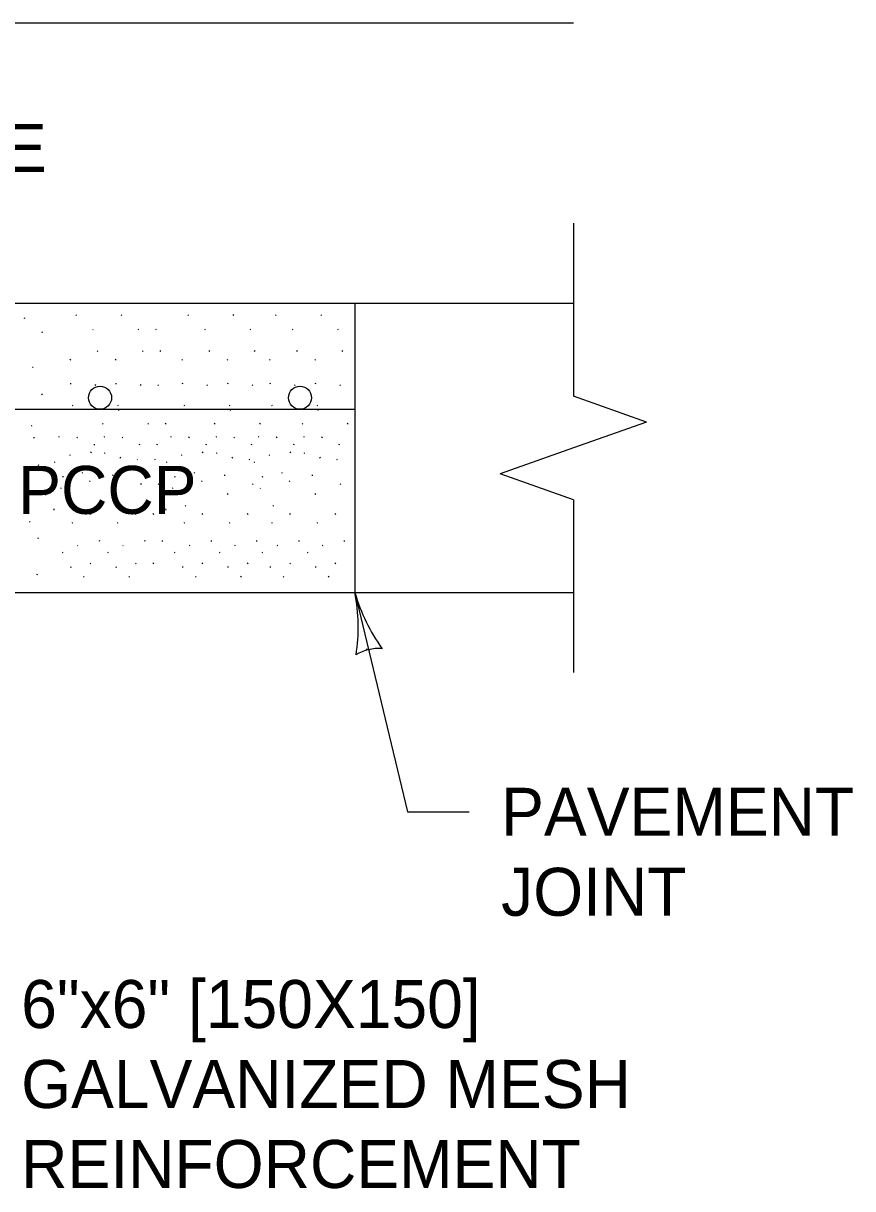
# Model space of a CAD drawing. Extents: x 49991.4 to 50029.7, y 49987.6 to 50011.4.
# Drawn here: x 50028.627 to 50029.664, y 49992.424 to 49993.881 of the extents above; entities that cross this region are included whole.
import ezdxf

# ---------------------------------------------------------------- set-up
doc = ezdxf.new("R2010")
doc.units = 0
for name, color, linetype in [('Level 1', 7, 'Continuous'), ('Level 2', 7, 'Continuous'), ('Level 3', 7, 'Continuous'), ('Level 4', 7, 'Continuous'), ('Level 5', 7, 'Continuous'), ('Level 6', 7, 'Continuous'), ('Level 9', 7, 'Continuous')]:
    doc.layers.add(name, color=color, linetype=linetype)

msp = doc.modelspace()

# ---------------------------------------------------------------- linework, layer by layer
at = {"layer": 'Level 1'}
for p, q in [((50028.0661, 49993.5314), (50029.3148, 49993.5314)), ((50029.0416, 49993.5313), (50029.0416, 49993.1697)), ((50028.0624, 49993.1696), (50029.3148, 49993.1696))]:
    msp.add_line(p, q, dxfattribs=at)
for centre in [(50028.723, 49993.4133), (50028.973, 49993.4133)]:
    msp.add_circle(centre, 0.0144, dxfattribs=at)
at = {"layer": 'Level 3'}
for p, q in [((50029.0416, 49993.1696), (50029.1073, 49992.8956)), ((50029.1073, 49992.8956), (50029.1845, 49992.8956))]:
    msp.add_line(p, q, dxfattribs=at)
for centre, radius, start, end in [((50028.8235, 49993.1267), 0.2223, 350.9492, 11.1327), ((50029.2652, 49993.2351), 0.233, 196.3205, 215.5704), ((50029.0715, 49993.045), 0.0548, 85.632, 121.3544)]:
    msp.add_arc(centre, radius, start, end, dxfattribs=at)
at = {"layer": 'Level 4'}
msp.add_line((50027.9165, 49993.3989), (50029.0416, 49993.3989), dxfattribs=at)
at = {"layer": 'Level 5'}
msp.add_line((50029.3148, 49993.8814), (50026.0794, 49993.8814), dxfattribs=at)
at = {"layer": 'Level 6'}
for p, q in [((50029.3148, 49993.6314), (50029.3148, 49993.4153)), ((50029.4062, 49993.3829), (50029.3148, 49993.4153)), ((50029.4062, 49993.3829), (50029.3148, 49993.3505)), ((50029.3148, 49993.3505), (50029.2234, 49993.3181)), ((50029.3148, 49993.2857), (50029.2234, 49993.3181)), ((50029.3148, 49993.2857), (50029.3148, 49993.0696))]:
    msp.add_line(p, q, dxfattribs=at)
at = {"layer": 'Level 9'}
for p, q in [((50028.6937, 49993.516), (50028.6927, 49993.5168)), ((50028.7504, 49993.516), (50028.7494, 49993.5168)), ((50028.8336, 49993.516), (50028.8326, 49993.5168)), ((50028.8902, 49993.516), (50028.8892, 49993.5168)), ((50028.9432, 49993.516), (50028.9422, 49993.5168)), ((50028.9999, 49993.516), (50028.9989, 49993.5168)), ((50028.6285, 49993.5134), (50028.6283, 49993.5121)), ((50028.6509, 49993.4951), (50028.65, 49993.4948)), ((50028.7146, 49993.4985), (50028.7138, 49993.4981)), ((50028.7712, 49993.4985), (50028.7704, 49993.4981)), ((50028.7932, 49993.4985), (50028.7924, 49993.4981)), ((50028.8545, 49993.4985), (50028.8537, 49993.4981)), ((50028.9111, 49993.4985), (50028.9103, 49993.4981)), ((50028.9641, 49993.4985), (50028.9633, 49993.4981)), ((50029.0207, 49993.4985), (50029.0199, 49993.4981)), ((50028.6864, 49993.4603), (50028.6853, 49993.4612)), ((50028.7203, 49993.4712), (50028.7193, 49993.4721)), ((50028.743, 49993.4603), (50028.742, 49993.4612)), ((50028.7769, 49993.4712), (50028.7759, 49993.4721)), ((50028.7989, 49993.4712), (50028.7979, 49993.4721)), ((50028.8262, 49993.4603), (50028.8252, 49993.4612)), ((50028.8602, 49993.4712), (50028.8592, 49993.4721)), ((50028.8828, 49993.4603), (50028.8818, 49993.4612)), ((50028.9168, 49993.4712), (50028.9158, 49993.4721)), ((50028.9359, 49993.4603), (50028.9348, 49993.4612)), ((50028.9698, 49993.4712), (50028.9688, 49993.4721)), ((50028.9925, 49993.4603), (50028.9915, 49993.4612)), ((50029.0264, 49993.4712), (50029.0254, 49993.4721)), ((50028.6394, 49993.4512), (50028.6386, 49993.4509)), ((50028.6861, 49993.4315), (50028.6859, 49993.4302)), ((50028.7176, 49993.4288), (50028.7166, 49993.4296)), ((50028.7428, 49993.4315), (50028.7426, 49993.4302)), ((50028.7743, 49993.4288), (50028.7733, 49993.4296)), ((50028.7962, 49993.4288), (50028.7952, 49993.4296)), ((50028.826, 49993.4315), (50028.8258, 49993.4302)), ((50028.8575, 49993.4288), (50028.8565, 49993.4296)), ((50028.8826, 49993.4315), (50028.8824, 49993.4302)), ((50028.9141, 49993.4288), (50028.9131, 49993.4296)), ((50028.9356, 49993.4315), (50028.9354, 49993.4302)), ((50028.9671, 49993.4288), (50028.9661, 49993.4296)), ((50028.9923, 49993.4315), (50028.9921, 49993.4302)), ((50029.0238, 49993.4288), (50029.0228, 49993.4296)), ((50028.6511, 49993.4171), (50028.6501, 49993.418)), ((50028.6889, 49993.4036), (50028.688, 49993.4033)), ((50028.7455, 49993.4036), (50028.7447, 49993.4033)), ((50028.8287, 49993.4036), (50028.8279, 49993.4033)), ((50028.8854, 49993.4036), (50028.8845, 49993.4033)), ((50028.9384, 49993.4036), (50028.9375, 49993.4033)), ((50028.995, 49993.4036), (50028.9942, 49993.4033)), ((50028.7464, 49993.3977), (50028.7456, 49993.3974)), ((50028.8863, 49993.3977), (50028.8855, 49993.3974)), ((50028.9959, 49993.3977), (50028.9951, 49993.3974)), ((50028.6377, 49993.378), (50028.6369, 49993.3776)), ((50028.727, 49993.3803), (50028.726, 49993.3811)), ((50028.7836, 49993.3803), (50028.7826, 49993.3811)), ((50028.8056, 49993.3803), (50028.8046, 49993.3811)), ((50028.8668, 49993.3803), (50028.8658, 49993.3811)), ((50028.9235, 49993.3803), (50028.9224, 49993.3811)), ((50028.9765, 49993.3803), (50028.9755, 49993.3811)), ((50029.0331, 49993.3803), (50029.0321, 49993.3811)), ((50028.6402, 49993.3641), (50028.6404, 49993.3627)), ((50028.672, 49993.3645), (50028.6712, 49993.3641)), ((50028.6948, 49993.363), (50028.6938, 49993.3638)), ((50028.7287, 49993.3645), (50028.7279, 49993.3641)), ((50028.7515, 49993.363), (50028.7505, 49993.3638)), ((50028.8119, 49993.3645), (50028.8111, 49993.3641)), ((50028.8347, 49993.363), (50028.8337, 49993.3638)), ((50028.8685, 49993.3645), (50028.8677, 49993.3641)), ((50028.8913, 49993.363), (50028.8903, 49993.3638)), ((50028.9215, 49993.3645), (50028.9207, 49993.3641)), ((50028.9443, 49993.363), (50028.9433, 49993.3638)), ((50028.9782, 49993.3645), (50028.9774, 49993.3641)), ((50029.001, 49993.363), (50029, 49993.3638)), ((50028.7122, 49993.3446), (50028.7112, 49993.3455)), ((50028.7157, 49993.3553), (50028.7155, 49993.354)), ((50028.7291, 49993.3438), (50028.7283, 49993.3435)), ((50028.7723, 49993.3553), (50028.7721, 49993.354)), ((50028.7943, 49993.3553), (50028.7941, 49993.354)), ((50028.852, 49993.3446), (50028.851, 49993.3455)), ((50028.8556, 49993.3553), (50028.8553, 49993.354)), ((50028.869, 49993.3438), (50028.8681, 49993.3435)), ((50028.9122, 49993.3553), (50028.912, 49993.354)), ((50028.9617, 49993.3446), (50028.9607, 49993.3455)), ((50028.9652, 49993.3553), (50028.965, 49993.354)), ((50028.9786, 49993.3438), (50028.9778, 49993.3435)), ((50029.0218, 49993.3553), (50029.0216, 49993.354)), ((50028.646, 49993.3294), (50028.6458, 49993.3281)), ((50028.6665, 49993.3328), (50028.6657, 49993.3324)), ((50028.6855, 49993.3414), (50028.6847, 49993.341)), ((50028.7491, 49993.3379), (50028.7481, 49993.3388)), ((50028.77, 49993.3361), (50028.7692, 49993.3358)), ((50028.792, 49993.3361), (50028.7912, 49993.3358)), ((50028.8064, 49993.3328), (50028.8056, 49993.3324)), ((50028.8254, 49993.3414), (50028.8246, 49993.341)), ((50028.8889, 49993.3379), (50028.8879, 49993.3388)), ((50028.9099, 49993.3361), (50028.9091, 49993.3358)), ((50028.916, 49993.3328), (50028.9152, 49993.3324)), ((50028.935, 49993.3414), (50028.9342, 49993.341)), ((50028.9986, 49993.3379), (50028.9976, 49993.3388)), ((50029.0195, 49993.3361), (50029.0187, 49993.3358)), ((50028.6763, 49993.3153), (50028.6765, 49993.3139)), ((50028.7016, 49993.3188), (50028.7006, 49993.3196)), ((50028.7388, 49993.317), (50028.7386, 49993.3156)), ((50028.8162, 49993.3153), (50028.8163, 49993.3139)), ((50028.8415, 49993.3188), (50028.8405, 49993.3196)), ((50028.8787, 49993.317), (50028.8785, 49993.3156)), ((50028.9258, 49993.3153), (50028.926, 49993.3139)), ((50028.9511, 49993.3188), (50028.9501, 49993.3196)), ((50028.9883, 49993.317), (50028.9881, 49993.3156)), ((50028.6743, 49993.3004), (50028.6735, 49993.3)), ((50028.7108, 49993.3086), (50028.7098, 49993.3095)), ((50028.7747, 49993.3048), (50028.7737, 49993.3057)), ((50028.7967, 49993.3048), (50028.7957, 49993.3057)), ((50028.8142, 49993.3004), (50028.8133, 49993.3)), ((50028.8507, 49993.3086), (50028.8497, 49993.3095)), ((50028.9146, 49993.3048), (50028.9136, 49993.3057)), ((50028.9238, 49993.3004), (50028.923, 49993.3)), ((50028.9603, 49993.3086), (50028.9593, 49993.3095)), ((50029.0242, 49993.3048), (50029.0232, 49993.3057)), ((50028.6553, 49993.2918), (50028.6545, 49993.2915)), ((50028.7432, 49993.2923), (50028.7422, 49993.2932)), ((50028.8831, 49993.2923), (50028.8821, 49993.2932)), ((50028.9927, 49993.2923), (50028.9917, 49993.2932)), ((50028.6651, 49993.2743), (50028.6652, 49993.2729)), ((50028.6904, 49993.2778), (50028.6894, 49993.2787)), ((50028.805, 49993.2743), (50028.8051, 49993.2729)), ((50028.8303, 49993.2778), (50028.8293, 49993.2787)), ((50028.9399, 49993.2778), (50028.9389, 49993.2787)), ((50028.6358, 49993.2577), (50028.6348, 49993.2586)), ((50028.6887, 49993.257), (50028.6879, 49993.2566)), ((50028.7116, 49993.2675), (50028.7106, 49993.2684)), ((50028.7454, 49993.257), (50028.7446, 49993.2566)), ((50028.7682, 49993.2675), (50028.7672, 49993.2684)), ((50028.7902, 49993.2675), (50028.7892, 49993.2684)), ((50028.8286, 49993.257), (50028.8278, 49993.2566)), ((50028.8515, 49993.2675), (50028.8505, 49993.2684)), ((50028.8852, 49993.257), (50028.8844, 49993.2566)), ((50028.9081, 49993.2675), (50028.9071, 49993.2684)), ((50028.9382, 49993.257), (50028.9374, 49993.2566)), ((50028.9611, 49993.2675), (50028.9601, 49993.2684)), ((50028.9949, 49993.257), (50028.9941, 49993.2566)), ((50029.0177, 49993.2675), (50029.0167, 49993.2684)), ((50028.6456, 49993.2381), (50028.6454, 49993.2368)), ((50028.6954, 49993.2284), (50028.6946, 49993.228)), ((50028.7222, 49993.235), (50028.722, 49993.2337)), ((50028.7521, 49993.2284), (50028.7513, 49993.228)), ((50028.7788, 49993.235), (50028.7786, 49993.2337)), ((50028.8008, 49993.235), (50028.8006, 49993.2337)), ((50028.8353, 49993.2284), (50028.8345, 49993.228)), ((50028.8621, 49993.235), (50028.8618, 49993.2337)), ((50028.8919, 49993.2284), (50028.8911, 49993.228)), ((50028.9187, 49993.235), (50028.9185, 49993.2337)), ((50028.9449, 49993.2284), (50028.9441, 49993.228)), ((50028.9717, 49993.235), (50028.9715, 49993.2337)), ((50029.0016, 49993.2284), (50029.0008, 49993.228)), ((50029.0283, 49993.235), (50029.0281, 49993.2337)), ((50028.6764, 49993.2198), (50028.6756, 49993.2194)), ((50028.7331, 49993.2198), (50028.7323, 49993.2194)), ((50028.8163, 49993.2198), (50028.8155, 49993.2194)), ((50028.8729, 49993.2198), (50028.8721, 49993.2194)), ((50028.9259, 49993.2198), (50028.9251, 49993.2194)), ((50028.9826, 49993.2198), (50028.9818, 49993.2194)), ((50028.6862, 49993.2023), (50028.6864, 49993.2009)), ((50028.7116, 49993.2058), (50028.7105, 49993.2066)), ((50028.7429, 49993.2023), (50028.743, 49993.2009)), ((50028.7682, 49993.2058), (50028.7672, 49993.2066)), ((50028.7902, 49993.2058), (50028.7891, 49993.2066)), ((50028.8261, 49993.2023), (50028.8262, 49993.2009)), ((50028.8514, 49993.2058), (50028.8504, 49993.2066)), ((50028.8827, 49993.2023), (50028.8829, 49993.2009)), ((50028.9081, 49993.2058), (50028.907, 49993.2066)), ((50028.9358, 49993.2023), (50028.9359, 49993.2009)), ((50028.9611, 49993.2058), (50028.9601, 49993.2066)), ((50028.9924, 49993.2023), (50028.9925, 49993.2009)), ((50029.0177, 49993.2058), (50029.0167, 49993.2066)), ((50028.6442, 49993.1927), (50028.644, 49993.1914)), ((50028.7033, 49993.189), (50028.7023, 49993.1898)), ((50028.7599, 49993.189), (50028.7589, 49993.1898)), ((50028.8432, 49993.189), (50028.8422, 49993.1898)), ((50028.8998, 49993.189), (50028.8988, 49993.1898)), ((50028.9528, 49993.189), (50028.9518, 49993.1898)), ((50029.0094, 49993.189), (50029.0084, 49993.1898)), ((50029.0558, 49993.0993), (50029.0571, 49993.0991))]:
    msp.add_line(p, q, dxfattribs=at)

# ---------------------------------------------------------------- texts
at = {"layer": 'Level 2'}
for s, p in [('FLOWLINE', (50028.2461, 49993.6955)), ('PCCP', (50028.6207, 49993.2681)), ('PAVEMENT', (50029.2245, 49992.8656)), ('JOINT', (50029.2245, 49992.7656)), ('6"x6" [150X150]', (50028.6244, 49992.6253)), ('GALVANIZED MESH', (50028.6244, 49992.5253)), ('REINFORCEMENT', (50028.6244, 49992.4253))]:
    msp.add_text(s, height=0.06, dxfattribs=at).set_placement(p)

doc.saveas('drawing.dxf')
